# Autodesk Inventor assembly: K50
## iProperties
Shininess: 64.0
Length Units: 11269
Angle Units: 11279
Time Units: 11290
Mass Units: 11283
Length Display Precision: 3
Angle Display Precision: 2
Compacted: True
Created: 2004-01
Part Number: K50
Document SubType Name: Assembly
Description: Kompaktspanner
Designer: Mittelmeyer
Manufacturer: Standard
Standards Organization: Custom
Vendor: TÜNKERS
Density: 0.0
Volumn: 0.0
Area: 0.0
PropertySet Name: Model Information
Control State: 0
Master: False
Checked Out: False
Author: Mittelmeyer
Comments: Tünkers
